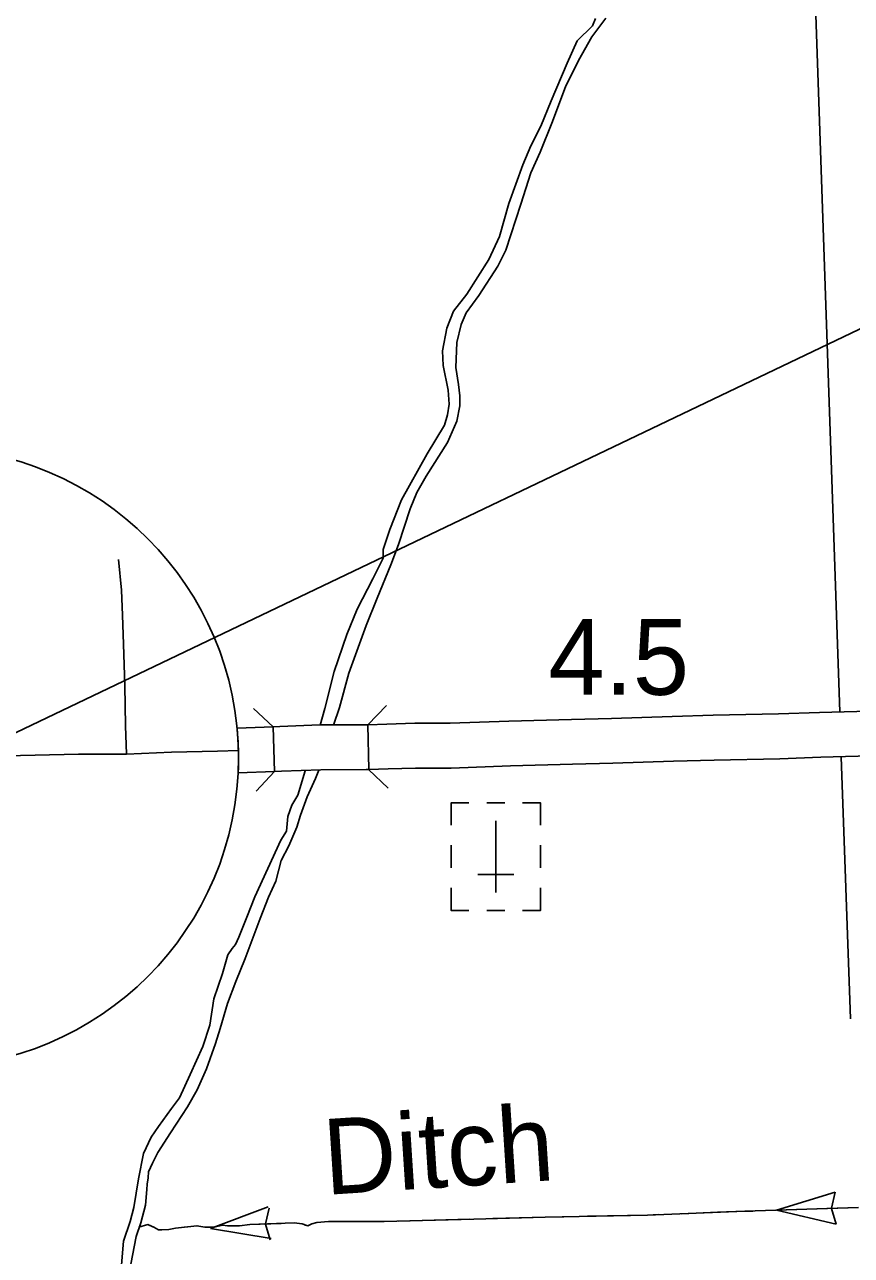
# Model space of a CAD drawing. Extents: x -117616 to 64730, y 54117 to 789866.
# Drawn here: x 62585 to 62677.4, y 54462.2 to 54599.6 of the extents above; entities that cross this region are included whole.
import ezdxf

# ---------------------------------------------------------------- set-up
doc = ezdxf.new("R2010")
doc.units = 0
for name, color, linetype in [('10', 7, 'Continuous'), ('32', 7, 'Continuous'), ('35', 7, 'Continuous'), ('37', 7, 'Continuous'), ('43', 7, 'Continuous'), ('48', 7, 'Continuous'), ('5', 7, 'Continuous'), ('57', 7, 'Continuous'), ('63', 7, 'Continuous'), ('R_Dimension', 7, 'Continuous')]:
    doc.layers.add(name, color=color, linetype=linetype)

msp = doc.modelspace()

# ---------------------------------------------------------------- linework, layer by layer
at = {"layer": '10'}
for p, q in [((62612.75, 54521.23), (62612.92, 54516.23)), ((62623.33, 54521.46), (62623.45, 54516.46))]:
    msp.add_line(p, q, dxfattribs=at)
for points in [[(62720.73, 54524.36), (62719.33, 54524.31), (62710.92, 54523.96), (62707.72, 54523.87), (62702.12, 54523.63), (62694.71, 54523.46), (62687.32, 54523.23), (62680.7, 54523.02), (62673.78, 54522.83), (62669.23, 54522.67), (62661.91, 54522.51), (62657.35, 54522.39), (62650.54, 54522.16), (62646.08, 54522.04), (62639.1, 54521.86), (62632.53, 54521.62), (62628.58, 54521.62), (62625.46, 54521.53), (62623.33, 54521.46)], [(62608.73, 54521.09), (62612.75, 54521.23)], [(62623.33, 54521.46), (62623.07, 54521.45), (62617.96, 54521.43), (62613.52, 54521.25), (62612.75, 54521.23)], [(62623.45, 54516.46), (62625.62, 54516.53), (62628.65, 54516.62), (62632.63, 54516.62), (62639.26, 54516.87), (62646.21, 54517.04), (62650.69, 54517.16), (62657.5, 54517.39), (62662.03, 54517.51), (62669.37, 54517.67), (62673.94, 54517.83), (62680.85, 54518.02), (62687.47, 54518.23), (62694.85, 54518.46), (62702.29, 54518.63), (62707.9, 54518.88), (62711.09, 54518.96), (62719.52, 54519.31), (62720.91, 54519.36)], [(62582.94, 54517.99), (62591.01, 54518.17), (62596.39, 54518.19)], [(62608.88, 54518.59), (62606.56, 54518.51), (62601.39, 54518.4), (62596.39, 54518.19)], [(62612.92, 54516.23), (62608.85, 54516.09)], [(62623.45, 54516.46), (62623.16, 54516.45), (62618.07, 54516.43), (62613.71, 54516.26), (62612.92, 54516.23)]]:
    msp.add_lwpolyline(points, dxfattribs=at)
msp.add_arc((62574.33, 54517.79), 34.56, 357.1745, 5.4708, dxfattribs=at)
at = {"layer": '32'}
msp.add_lwpolyline([(62596.39, 54518.19), (62596.27, 54521.33), (62596.19, 54525.84), (62596.05, 54530.47), (62595.93, 54533.7), (62595.82, 54536.48), (62595.48, 54539.92)], dxfattribs=at)
at = {"layer": '35'}
for points in [[(62619.52, 54521.42), (62620.16, 54523.37), (62621.2, 54527.21), (62623.15, 54532.53), (62624.37, 54535.58), (62625.89, 54539.33), (62626.78, 54541.57), (62628.05, 54545.55), (62628.83, 54547.4), (62629.85, 54549.2), (62632.23, 54552.96), (62633.29, 54555.37), (62633.62, 54557.07), (62633.62, 54558.19), (62633.45, 54559.45), (62633.17, 54561.36), (62633.29, 54564.15), (62633.75, 54566.15), (62634.33, 54567.45), (62635.75, 54569.4), (62637.86, 54572.65), (62638.77, 54574.45), (62639.3, 54576.15), (62640.42, 54579.6), (62641.56, 54583.08), (62642.6, 54585.39), (62643.97, 54588.81), (62644.8, 54591.02), (62645.41, 54592.67), (62646.88, 54595.61), (62648.35, 54598.25), (62649.92, 54600.36)], [(62618.03, 54521.42), (62618.53, 54523.29), (62619.57, 54527.41), (62621, 54531.53), (62622.13, 54534.35), (62623.9, 54537.75), (62625.04, 54540.04), (62625.04, 54541.01), (62625.8, 54543.25), (62627.11, 54546.56), (62629.97, 54551.72), (62631.92, 54554.9), (62632.24, 54556.06), (62632.41, 54557.24), (62632.33, 54558.82), (62631.77, 54561.56), (62631.69, 54563.21), (62632.16, 54565.73), (62632.9, 54567.63), (62634.4, 54569.55), (62636.85, 54573.4), (62638.03, 54575.97), (62639.09, 54579.67), (62640.64, 54583.99), (62641.53, 54586.11), (62642.66, 54588.31), (62643.8, 54591.12), (62645.62, 54595.31), (62646.73, 54597.81), (62648.43, 54599.48), (62648.78, 54600.3)], [(62617.88, 54516.4), (62617.51, 54515.44), (62616.57, 54513.42), (62615.8, 54511.37), (62615.41, 54510.02), (62614.53, 54507.92), (62613.67, 54506.31), (62613.05, 54503.98), (62612.25, 54502.19), (62611.32, 54499.83), (62609.63, 54495.37), (62608.6, 54492.8), (62607.66, 54490.34), (62606.83, 54487.56), (62606.34, 54485.88), (62605.33, 54483.05), (62604.27, 54480.71), (62603.21, 54478.8), (62601.29, 54475.89), (62599.89, 54473.71), (62599.3, 54472.52), (62598.83, 54471.53), (62598.8, 54470.86), (62598.7, 54470.16), (62598.65, 54469.56), (62598.52, 54467.8), (62597.97, 54465.86), (62597.46, 54464.3), (62596.86, 54461.24)], [(62615.52, 54513.58), (62616.33, 54516.31)], [(62595.77, 54460.7), (62596.04, 54463.78), (62596.8, 54466.01), (62597.2, 54467.54), (62597.72, 54470.77), (62598.27, 54473.58), (62599.12, 54475.41), (62599.97, 54476.6), (62601.41, 54478.61), (62602.29, 54479.8), (62603.48, 54482.4), (62604.91, 54485.54), (62605.7, 54487.92), (62606.13, 54490.85), (62607.11, 54493.69), (62607.69, 54495.76), (62608.17, 54496.46), (62608.57, 54496.92), (62608.91, 54497.75), (62609.82, 54499.97), (62610.73, 54502.23), (62613.63, 54508.58), (62614.24, 54509.56), (62614.42, 54511.2), (62614.85, 54512.49), (62615.52, 54513.58)]]:
    msp.add_lwpolyline(points, dxfattribs=at)
at = {"layer": '37'}
for points in [[(62623.33, 54521.46), (62625.41, 54523.62)], [(62610.56, 54523.27), (62612.75, 54521.23)], [(62612.92, 54516.23), (62610.88, 54514.04)], [(62625.6, 54514.38), (62623.43, 54516.46)]]:
    msp.add_lwpolyline(points, dxfattribs=at)
at = {"layer": '43'}
for p, q in [((62668.98, 54467.25), (62675.55, 54469.25)), ((62675.55, 54469.25), (62675.14, 54467.47)), ((62605.77, 54465.2), (62612.19, 54467.63)), ((62612.31, 54467.5), (62611.9, 54465.72)), ((62668.98, 54467.25), (62675.67, 54465.7)), ((62675.67, 54465.7), (62675.14, 54467.44)), ((62612.44, 54463.95), (62611.9, 54465.69)), ((62605.77, 54465.2), (62612.54, 54464.09))]:
    msp.add_line(p, q, dxfattribs=at)
for points in [[(62678.14, 54467.56), (62665.46, 54467.14), (62654.57, 54466.71), (62643.15, 54466.48), (62635.18, 54466.25), (62625.18, 54465.98), (62621, 54465.98), (62618.93, 54465.98), (62617.66, 54465.87), (62617.09, 54465.72), (62616.63, 54465.52), (62616.02, 54465.72), (62615.1, 54465.83), (62610.15, 54465.64), (62609, 54465.52), (62607.66, 54465.52), (62607.09, 54465.6), (62606.17, 54465.37), (62605.13, 54465.37), (62604.25, 54465.52), (62601.87, 54465.26), (62601.11, 54465.1), (62600.34, 54465.06), (62599.96, 54465.06), (62599.42, 54465.37), (62598.77, 54465.64), (62597.77, 54465.37)], [(62666.35, 54467.16), (62665.46, 54467.14), (62662.39, 54467.02)], [(62676.9, 54467.52), (62668.98, 54467.25)], [(62613.66, 54465.78), (62610.15, 54465.64), (62609, 54465.52), (62607.66, 54465.52), (62607.09, 54465.6), (62606.17, 54465.37), (62605.79, 54465.37)], [(62624.12, 54465.98), (62621, 54465.98), (62618.93, 54465.98), (62617.66, 54465.87), (62617.09, 54465.72), (62616.63, 54465.52), (62616.28, 54465.63)], [(62634.68, 54466.24), (62626.76, 54466.03)], [(62645.24, 54466.52), (62643.15, 54466.48), (62637.32, 54466.31)], [(62655.79, 54466.76), (62654.57, 54466.71), (62647.88, 54466.58)], [(62662.39, 54467.02), (62658.43, 54466.86)], [(62599.32, 54465.41), (62598.77, 54465.64), (62597.77, 54465.37)], [(62603.17, 54465.4), (62601.87, 54465.26), (62601.11, 54465.1), (62600.34, 54465.06), (62599.96, 54465.06), (62599.42, 54465.37), (62599.32, 54465.41)]]:
    msp.add_lwpolyline(points, dxfattribs=at)
at = {"layer": '5'}
for points in [[(62672.48, 54626.7), (62676.05, 54522.89)], [(62676.22, 54517.89), (62677.26, 54488.64)]]:
    msp.add_lwpolyline(points, dxfattribs=at)
at = {"layer": '57'}
for p, q in [((62636.64, 54512.73), (62638.64, 54512.73)), ((62637.63, 54502.73), (62637.63, 54510.73)), ((62632.63, 54505.5), (62632.63, 54508)), ((62642.63, 54506.73), (62642.63, 54508)), ((62637.63, 54506.73), (62637.63, 54506.73)), ((62637.63, 54506.73), (62637.63, 54506.73)), ((62642.63, 54506.73), (62642.63, 54505.5)), ((62635.63, 54504.73), (62639.65, 54504.73)), ((62638.64, 54500.73), (62636.64, 54500.73))]:
    msp.add_line(p, q, dxfattribs=at)
for points in [[(62634.63, 54512.73), (62632.63, 54512.73), (62632.63, 54510.23)], [(62642.63, 54510.23), (62642.63, 54512.73), (62640.63, 54512.73)], [(62634.63, 54500.73), (62632.63, 54500.73), (62632.63, 54503.23)], [(62640.63, 54500.73), (62642.63, 54500.73), (62642.63, 54503.23)]]:
    msp.add_lwpolyline(points, dxfattribs=at)
at = {"layer": '63'}
msp.add_circle((62574.33, 54517.79), 34.56, dxfattribs=at)
at = {"layer": 'R_Dimension'}
msp.add_lwpolyline([(62940.1, 54690.83), (62215.14, 54344.27), (61753.25, 54344.27)], dxfattribs=at)

# ---------------------------------------------------------------- texts
at = {"layer": '43'}
msp.add_text('Ditch', height=8.448, rotation=3.6945, dxfattribs=at).set_placement((62618.63, 54468.96))
at = {"layer": '48'}
msp.add_text('4.5', height=8.448, dxfattribs=at).set_placement((62643.52, 54524.8))

doc.saveas('drawing.dxf')
